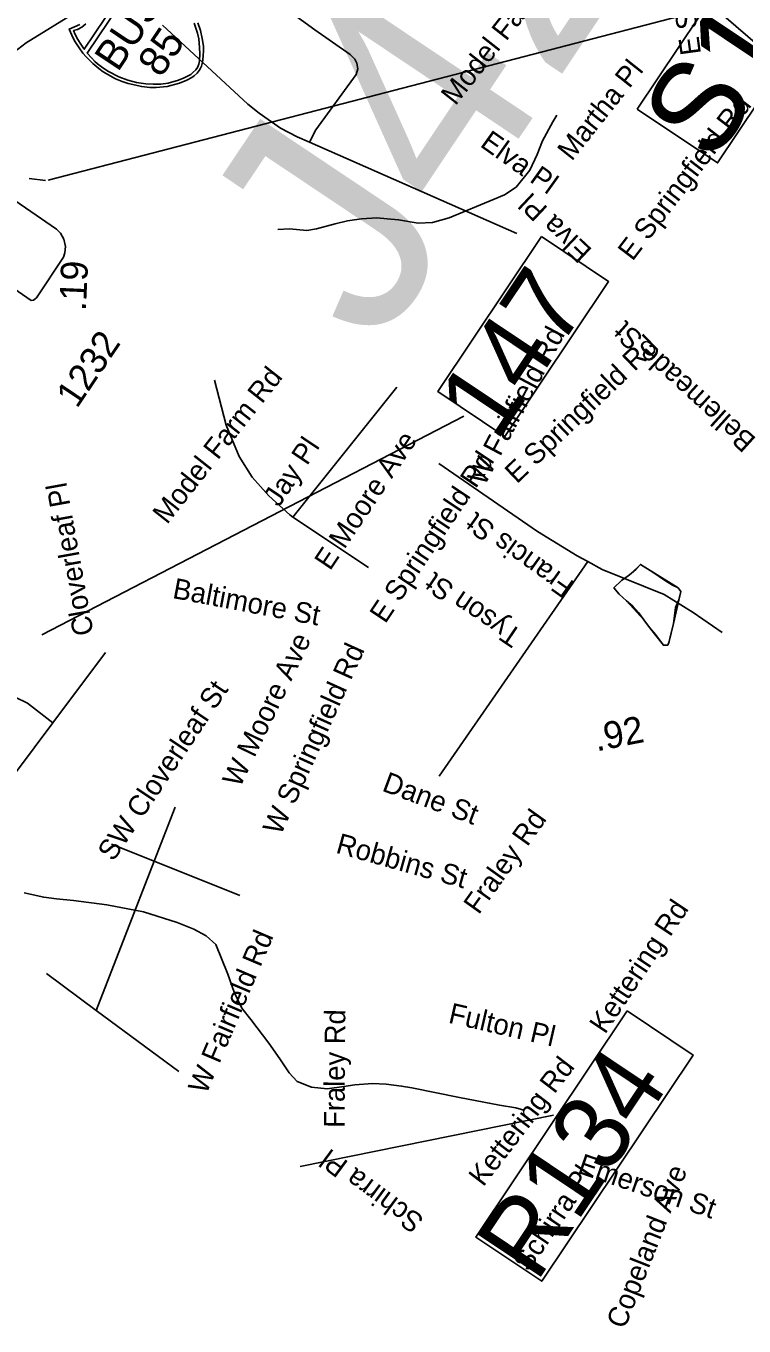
# Model space of a CAD drawing. Extents: x 1716282 to 1717158, y 799307 to 801078.
# Drawn here: x 1716928.3 to 1716976.7, y 800646 to 800733.7 of the extents above; entities that cross this region are included whole.
import ezdxf

# ---------------------------------------------------------------- set-up
doc = ezdxf.new("R2010")
doc.units = 0
for name, color, linetype in [('Exist Hydrographic Misc Water Feature', 7, 'Continuous'), ('Exist Railroad Structure Bridge Number Label', 7, 'Continuous'), ('Exist Road Non-System Structure Non-Sys Other Number Label', 7, 'Continuous'), ('Exist Road Non-System Type 51', 7, 'Continuous'), ('Exist Road Non-System Type 51 Label', 7, 'Continuous'), ('Exist Road Primary Interstate Shield CELL', 7, 'Continuous'), ('Exist Road Primary Interstate Shield Number Label', 7, 'Continuous'), ('Exist Road Primary Interstate Structure Ovrhead Sign CELL', 7, 'Continuous'), ('Exist Road Primary Interstate Structure Standard Bridge Number Label', 7, 'Continuous'), ('Exist Road Primary US Mileage Hundredths English Label', 7, 'Continuous'), ('Exist Road Secondary Mileage Hundredths English Label', 7, 'Continuous'), ('Exist Road Secondary Type 51 Label', 7, 'Continuous'), ('Exist Road Secondary Type 51 Number Label', 7, 'Continuous')]:
    doc.layers.add(name, color=color, linetype=linetype)

msp = doc.modelspace()

# ---------------------------------------------------------------- linework, layer by layer
at = {"layer": 'Exist Hydrographic Misc Water Feature'}
for points in [[(1716945.308, 800719.941), (1716946.112, 800719.989), (1716947.261, 800719.871), (1716947.931, 800719.976), (1716949.182, 800720.316), (1716950.021, 800720.516), (1716950.956, 800720.649), (1716951.986, 800720.718), (1716952.686, 800720.663), (1716953.45, 800720.599), (1716954.766, 800720.366), (1716955.739, 800720.403), (1716956.87, 800720.719), (1716959.909, 800721.98), (1716960.605, 800722.279), (1716961.384, 800722.802), (1716962.297, 800723.933), (1716962.808, 800724.99), (1716963.156, 800725.911), (1716963.854, 800727.19), (1716964.124, 800727.637)], [(1716969.127, 800696.75), (1716969.468, 800697.044), (1716969.761, 800697.37), (1716970.593, 800696.838), (1716971.383, 800696.299), (1716971.926, 800695.961), (1716972.294, 800695.781), (1716972.485, 800695.546), (1716972.341, 800694.976), (1716972.126, 800694.455), (1716971.994, 800693.386), (1716971.792, 800692.577), (1716971.698, 800692.183), (1716971.6, 800691.936), (1716971.309, 800691.923), (1716970.778, 800692.636), (1716970.373, 800693.122), (1716969.986, 800693.635), (1716969.62, 800694.13), (1716969.248, 800694.56), (1716968.825, 800694.92), (1716968.323, 800695.367), (1716967.974, 800695.781), (1716968.486, 800696.274), (1716968.924, 800696.607), (1716969.127, 800696.75)], [(1716969.127, 800696.75), (1716969.761, 800697.37), (1716972.294, 800695.781), (1716972.485, 800695.546), (1716971.994, 800693.386), (1716971.698, 800692.183), (1716971.6, 800691.936), (1716971.309, 800691.923), (1716970.373, 800693.122), (1716969.986, 800693.635), (1716968.825, 800694.92), (1716968.323, 800695.367), (1716967.974, 800695.781), (1716968.486, 800696.274), (1716968.924, 800696.607), (1716969.127, 800696.75)], [(1716928.22, 800675.23), (1716929.53, 800674.935), (1716930.405, 800674.829), (1716931.53, 800674.727), (1716933.779, 800674.42), (1716936.268, 800673.949), (1716938.529, 800673.247), (1716939.659, 800672.793), (1716940.474, 800672.34), (1716941.127, 800671.754), (1716941.941, 800669.757), (1716942.378, 800668.547), (1716942.897, 800667.453), (1716943.5, 800666.692), (1716944.698, 800665.102), (1716945.457, 800664.053), (1716946.076, 800663.106), (1716946.624, 800662.521), (1716947.593, 800662.139), (1716948.637, 800662.023), (1716949.773, 800662.194), (1716950.507, 800662.29), (1716951.698, 800662.391), (1716952.607, 800662.332), (1716953.652, 800662.215), (1716954.343, 800662.095), (1716957.553, 800661.447), (1716960.259, 800660.935), (1716961.36, 800660.745), (1716961.889, 800660.594)]]:
    msp.add_lwpolyline(points, dxfattribs=at)
at = {"layer": 'Exist Railroad Structure Bridge Number Label'}
msp.add_line((1716946.824, 800656.783), (1716963.899, 800660.263), dxfattribs=at)
msp.add_lwpolyline([(1716968.867, 800667.28), (1716958.66, 800652.031), (1716963.104, 800649.057), (1716973.311, 800664.306)], close=True, dxfattribs=at)
at = {"layer": 'Exist Road Non-System Type 51'}
for p, q in [((1716947.442, 800725.829), (1716961.429, 800719.664)), ((1716953.344, 800709.322), (1716946.328, 800700.559)), ((1716946.328, 800700.559), (1716951.417, 800697.153)), ((1716966.212, 800697.554), (1716956.181, 800683.094)), ((1716933.699, 800691.428), (1716930.146, 800686.692)), ((1716930.146, 800686.692), (1716921.919, 800675.727)), ((1716938.403, 800681.006), (1716936.983, 800677.359)), ((1716934.093, 800678.515), (1716936.983, 800677.359)), ((1716936.983, 800677.359), (1716933.069, 800667.311)), ((1716936.983, 800677.359), (1716942.761, 800675.066)), ((1716929.71, 800669.797), (1716933.069, 800667.311)), ((1716933.069, 800667.311), (1716938.635, 800663.187))]:
    msp.add_line(p, q, dxfattribs=at)
for points in [[(1716922.727, 800725.212), (1716926.19, 800730.332), (1716927.184, 800731.494), (1716927.773, 800732.066), (1716928.347, 800732.528), (1716931.933, 800734.726), (1716932.599, 800735.384), (1716933.015, 800735.986), (1716933.71, 800737.292)], [(1716972.807, 800736.581), (1716979.578, 800730.73)], [(1716943.8, 800736.323), (1716947.812, 800733.4), (1716950.186, 800731.728), (1716950.507, 800731.413), (1716950.647, 800731.158), (1716950.701, 800730.771), (1716950.59, 800730.395), (1716947.887, 800726.663), (1716947.442, 800725.829)], [(1716937.546, 800733.704), (1716943.303, 800728.394), (1716944.068, 800727.781), (1716945.506, 800726.758), (1716946.616, 800726.194), (1716947.442, 800725.829)], [(1716925.455, 800717.382), (1716928.696, 800715.159), (1716928.835, 800715.181), (1716929.05, 800715.343), (1716930.874, 800718.082), (1716930.966, 800718.357), (1716931.012, 800718.788), (1716930.899, 800719.298), (1716930.669, 800719.701), (1716930.396, 800719.955), (1716922.727, 800725.212)], [(1716941.053, 800709.795), (1716941.832, 800706.753), (1716942.702, 800704.652), (1716943.583, 800703.258), (1716944.713, 800701.998), (1716946.115, 800700.706), (1716946.328, 800700.559)], [(1716956.166, 800704.16), (1716962.83, 800699.59), (1716965.503, 800697.947), (1716966.212, 800697.554)], [(1716966.212, 800697.554), (1716967.171, 800697.036), (1716971.35, 800695.338), (1716973.315, 800694.134), (1716975.263, 800692.773)], [(1716916.976, 800692.55), (1716917.535, 800692.079), (1716918.912, 800691.131), (1716919.845, 800690.583), (1716920.955, 800690.052), (1716922.244, 800689.664), (1716924.707, 800689.423), (1716925.54, 800689.225), (1716926.785, 800688.82), (1716928.443, 800688.015), (1716930.146, 800686.692)]]:
    msp.add_lwpolyline(points, dxfattribs=at)
at = {"layer": 'Exist Road Primary Interstate Shield CELL'}
for points in [[(1716932.379, 800733.793), (1716932.097, 800733.58), (1716931.812, 800733.423), (1716931.545, 800733.345), (1716931.661, 800733.076), (1716931.834, 800732.739), (1716932.037, 800732.426), (1716932.269, 800732.09), (1716935.751, 800737.289)], [(1716939.678, 800733.849), (1716939.84, 800733.366), (1716939.905, 800733.16), (1716939.987, 800732.796), (1716940.039, 800732.199), (1716940.061, 800731.774), (1716940.034, 800731.301), (1716939.995, 800731.077), (1716939.903, 800730.848), (1716939.781, 800730.691), (1716939.593, 800730.526), (1716939.441, 800730.393), (1716939.011, 800730.167), (1716938.627, 800730.008), (1716937.913, 800729.792), (1716937.438, 800729.736), (1716936.922, 800729.731), (1716936.415, 800729.759), (1716935.783, 800729.849), (1716935.194, 800730.009), (1716934.596, 800730.238), (1716933.908, 800730.583), (1716933.516, 800730.833), (1716933.16, 800731.105), (1716932.989, 800731.271), (1716932.779, 800731.48), (1716932.469, 800731.824), (1716936.028, 800737.148)], [(1716931.961, 800733.76), (1716931.252, 800733.448), (1716931.419, 800733.027), (1716931.609, 800732.647), (1716931.918, 800732.172), (1716932.176, 800731.833), (1716932.397, 800731.567), (1716932.835, 800731.127), (1716933.241, 800730.781), (1716933.546, 800730.563), (1716934.362, 800730.1), (1716934.832, 800729.908), (1716935.225, 800729.771), (1716936.141, 800729.574), (1716936.691, 800729.519), (1716937.107, 800729.51), (1716937.608, 800729.551), (1716937.859, 800729.587), (1716938.692, 800729.811), (1716939.18, 800730.007), (1716939.528, 800730.191), (1716939.67, 800730.292), (1716939.871, 800730.464), (1716940.023, 800730.644), (1716940.089, 800730.766), (1716940.162, 800730.939), (1716940.213, 800731.121), (1716940.251, 800731.342), (1716940.28, 800731.686), (1716940.297, 800731.967), (1716940.296, 800732.305), (1716940.221, 800732.811), (1716940.101, 800733.346), (1716939.912, 800733.873)]]:
    msp.add_lwpolyline(points, dxfattribs=at)
at = {"layer": 'Exist Road Primary Interstate Structure Ovrhead Sign CELL'}
for p, q in [((1716929.831, 800723.268), (1716974.138, 800734.767)), ((1716928.562, 800723.383), (1716929.652, 800723.236))]:
    msp.add_line(p, q, dxfattribs=at)
msp.add_lwpolyline([(1716969.549, 800728.043), (1716984.84, 800750.889), (1716990.251, 800747.268), (1716974.959, 800724.421)], close=True, dxfattribs=at)
at = {"layer": 'Exist Road Primary Interstate Structure Standard Bridge Number Label'}
msp.add_line((1716929.416, 800692.627), (1716957.861, 800707.368), dxfattribs=at)
msp.add_lwpolyline([(1716963.089, 800719.464), (1716956.1, 800709.023), (1716960.627, 800705.993), (1716967.615, 800716.434)], close=True, dxfattribs=at)

# ---------------------------------------------------------------- texts
at = {"layer": 'Exist Railroad Structure Bridge Number Label'}
msp.add_text('R134', height=5.075, rotation=56.20506, dxfattribs=at).set_placement((1716962.737, 800648.896))
at = {"layer": 'Exist Road Non-System Structure Non-Sys Other Number Label'}
msp.add_text('J428', height=15.223, rotation=56.20506, dxfattribs=at).set_placement((1716951.956, 800711.723))
at = {"layer": 'Exist Road Non-System Type 51 Label'}
for s, rotation, p in [('E Springfield Rd', 97.74788, (1716973.844, 800731.788)), ('Model Farm Rd', 51.85229, (1716957.287, 800728.236)), ('Martha Pl', 51.57754, (1716965.127, 800724.497)), ('E Springfield Rd', 52.59426, (1716969.221, 800717.754)), ('Elva Pl', 324.52668, (1716958.882, 800725.579)), ('Elva Pl', 136.68745, (1716966.563, 800718.569)), ('Bellemeade St', 137.87806, (1716977.62, 800705.837)), ('E Springfield Rd', 43.66561, (1716961.425, 800702.759)), ('Model Farm Rd', 51.76586, (1716937.845, 800700.012)), ('Jay Pl', 56.01572, (1716945.389, 800701.175)), ('E Moore Ave', 56.20506, (1716948.835, 800696.893)), ('E Springfield Rd', 56.20506, (1716952.557, 800693.324)), ('Cloverleaf Pl', 100.28245, (1716932.907, 800692.694)), ('Francis St', 144.42888, (1716965.391, 800696.134)), ('Baltimore St', 349.27822, (1716938.161, 800695.109)), ('Tyson St', 145.94999, (1716961.879, 800692.839)), ('W Moore Ave', 64.33981, (1716942.76, 800682.265)), ('W Springfield Rd', 65.67287, (1716945.506, 800679.049)), ('SW Cloverleaf St', 56.20506, (1716934.22, 800677.288)), ('Dane St', 339.52706, (1716952.271, 800682.131)), ('Fraley Rd', 54.51043, (1716958.858, 800673.713)), ('Robbins St', 344.38729, (1716949.16, 800677.95)), ('Kettering Rd', 56.20506, (1716967.369, 800665.657)), ('Fulton Pl', 347.1001, (1716956.751, 800666.492)), ('Fraley Rd', 89.56923, (1716949.808, 800659.396)), ('Kettering Rd', 52.55971, (1716959.161, 800655.372)), ('Schirra Pl', 143.6303, (1716955.25, 800653.309)), ('Schirra Pl', 56.20506, (1716962.237, 800649.636)), ('Emerson St', 341.09955, (1716965.459, 800656.382)), ('Copeland Ave', 68.50739, (1716968.701, 800645.782))]:
    msp.add_text(s, height=1.3775, rotation=rotation, dxfattribs=at).set_placement(p)
at = {"layer": 'Exist Road Primary Interstate Shield Number Label'}
for s, p in [('BUS', (1716934.53, 800730.492)), ('85', (1716937.436, 800730.107))]:
    msp.add_text(s, height=2.03, rotation=56.20506, dxfattribs=at).set_placement(p)
at = {"layer": 'Exist Road Primary Interstate Structure Ovrhead Sign CELL'}
msp.add_text('S1065', height=6.09, rotation=56.20506, dxfattribs=at).set_placement((1716974.636, 800724.301))
at = {"layer": 'Exist Road Primary Interstate Structure Standard Bridge Number Label'}
msp.add_text('147', height=5.075, rotation=56.20506, dxfattribs=at).set_placement((1716960.057, 800705.548))
at = {"layer": 'Exist Road Primary US Mileage Hundredths English Label'}
msp.add_text('.92', height=1.8125, rotation=11.21944, dxfattribs=at).set_placement((1716966.801, 800684.761))
at = {"layer": 'Exist Road Secondary Mileage Hundredths English Label'}
msp.add_text('.19', height=1.8125, rotation=87.43655, dxfattribs=at).set_placement((1716932.375, 800714.427))
at = {"layer": 'Exist Road Secondary Type 51 Label'}
for rotation, p in [(62.1189, (1716959.246, 800702.598)), (66.97193, (1716940.488, 800661.597))]:
    msp.add_text('W Fairfield Rd', height=1.3775, rotation=rotation, dxfattribs=at).set_placement(p)
at = {"layer": 'Exist Road Secondary Type 51 Number Label'}
msp.add_text('1232', height=1.8125, rotation=56.20506, dxfattribs=at).set_placement((1716931.773, 800707.823))

doc.saveas('drawing.dxf')
